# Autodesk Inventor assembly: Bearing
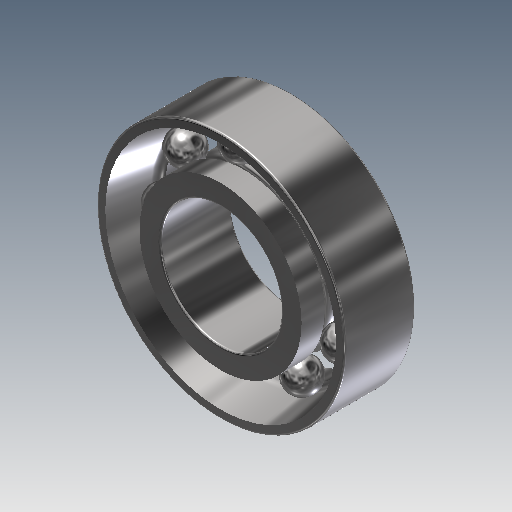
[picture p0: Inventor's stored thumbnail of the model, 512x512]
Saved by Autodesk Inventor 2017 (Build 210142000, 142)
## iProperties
Created: 2019-02
Part Number: Bearing
Document SubType Name: Assembly
Designer: user
Mass: 34.9637 g
Surface Area: 47.3243 cm^2
Volume: 4.45397 cm^3
Density: 7.85 g/cm^3
ClientObjectVersion: 1
Author: user
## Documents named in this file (2)
- C:\Users\user\Documents\EIA\Cursos\Diseño asistido por computador\Clase 7 Dynamic simulation\Ensamble reductor de velocidad\Ensamble\Design Accelerator\Bearing1.iam
- C:\Users\user\Documents\Inventor\Content Center Files\R2017\en-US\BS 292 (II)\BS 292_ Part 1 - 7003 - 17 x 35 x 10.ipt
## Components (1 placed, 1 different names)
1. BS 292: Part 1 (II) - Metric 7003 - 17 x 35 x 10:1
